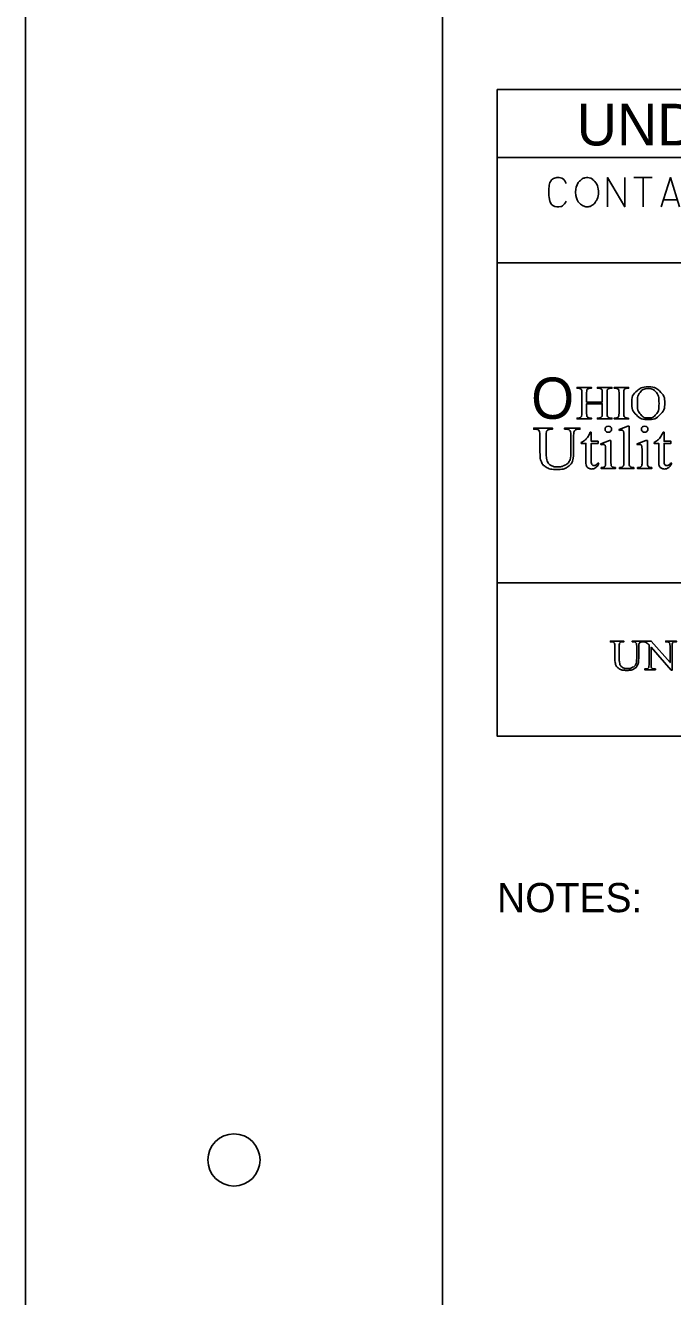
# Model space of a CAD drawing. Extents: x 0 to 34, y 0 to 22.
# Drawn here: x 0 to 3.1, y 6.09 to 12.19 of the extents above; entities that cross this region are included whole.
import ezdxf

# ---------------------------------------------------------------- set-up
doc = ezdxf.new("R2010")
doc.units = 0
for name, color, linetype in [('SH_Border', 7, 'Continuous'), ('SH_Cut_Line', 7, 'Continuous'), ('SH_Data', 7, 'Continuous'), ('SH_Text', 7, 'Continuous')]:
    doc.layers.add(name, color=color, linetype=linetype)

msp = doc.modelspace()

# ---------------------------------------------------------------- linework, layer by layer
at = {"layer": 'SH_Border'}
msp.add_lwpolyline([(2, 21.5), (33.5, 21.5), (33.5, 0.5), (2, 0.5)], close=True, dxfattribs=at)
msp.add_circle((1, 6.75), 0.125, dxfattribs=at)
at = {"layer": 'SH_Cut_Line'}
msp.add_lwpolyline([(0, 0), (34, 0), (34, 22), (0, 22)], close=True, dxfattribs=at)
at = {"layer": 'SH_Data'}
for p, q in [((2.2617, 11.5571), (7.4617, 11.5571)), ((2.918, 11.46), (3.0051, 11.46)), ((2.9621, 11.46), (2.9621, 11.32)), ((3.1253, 11.3531), (3.0602, 11.3531)), ((2.2617, 11.0512), (7.4617, 11.0512)), ((2.2617, 9.5165), (7.4617, 9.5165))]:
    msp.add_line(p, q, dxfattribs=at)
msp.add_lwpolyline([(2.2617, 11.8822), (7.4617, 11.8822), (7.4617, 8.7822), (2.2617, 8.7822)], close=True, dxfattribs=at)
msp.add_lwpolyline([(2.2617, 11.8822), (7.4617, 11.8822), (7.4617, 8.7822), (2.2617, 8.7822)], close=True, dxfattribs=at)
for points in [[(2.5929, 11.4325), (2.5874, 11.4446), (2.5818, 11.4512), (2.5763, 11.4556), (2.5719, 11.4578), (2.5598, 11.46), (2.5477, 11.46), (2.5322, 11.4556), (2.5234, 11.449), (2.519, 11.4435), (2.5146, 11.4358), (2.5113, 11.4237), (2.5102, 11.4016), (2.5102, 11.3851), (2.5102, 11.374), (2.5113, 11.3641), (2.5146, 11.3465), (2.5157, 11.3432), (2.5201, 11.3355), (2.5245, 11.33), (2.5322, 11.3244), (2.5389, 11.3222), (2.5477, 11.32), (2.5576, 11.32), (2.5675, 11.3211), (2.5708, 11.3222), (2.5752, 11.3244), (2.5796, 11.3289), (2.5851, 11.3344), (2.5896, 11.341), (2.5929, 11.3465)], [(2.6821, 11.4589), (2.6788, 11.4578), (2.6755, 11.4567), (2.67, 11.4534), (2.6667, 11.4512), (2.6612, 11.4468), (2.6568, 11.4424), (2.6546, 11.4402), (2.6513, 11.4358), (2.6458, 11.4247), (2.6414, 11.4137), (2.6392, 11.4038), (2.6381, 11.3895), (2.6392, 11.374), (2.6425, 11.363), (2.6458, 11.3542), (2.648, 11.3498), (2.6513, 11.3443), (2.6557, 11.3388), (2.659, 11.3355), (2.6623, 11.3322), (2.6667, 11.3289), (2.6722, 11.3255), (2.6821, 11.3211), (2.6877, 11.32), (2.6987, 11.32), (2.7031, 11.3211), (2.7075, 11.3222), (2.713, 11.3244), (2.7185, 11.3277), (2.7218, 11.33), (2.7251, 11.3322), (2.7284, 11.3355), (2.7317, 11.3399), (2.7339, 11.3432), (2.7362, 11.3465), (2.7384, 11.3498), (2.7417, 11.3564), (2.745, 11.3641), (2.7472, 11.3729), (2.7483, 11.3807), (2.7483, 11.3818), (2.7483, 11.3895), (2.7483, 11.3961), (2.7472, 11.4049), (2.745, 11.4137), (2.7428, 11.4203), (2.7395, 11.4281), (2.7362, 11.4347), (2.7306, 11.4413), (2.7262, 11.4457), (2.7218, 11.4501), (2.7174, 11.4534), (2.7108, 11.4567), (2.7042, 11.4589), (2.6976, 11.46), (2.6899, 11.46), (2.6821, 11.4589)], [(2.7913, 11.32), (2.7913, 11.46), (2.8739, 11.32), (2.8739, 11.46)], [(3.0492, 11.32), (3.0933, 11.46), (3.1363, 11.32)], [(2.651, 10.4499), (2.6453, 10.4499), (2.6453, 10.454), (2.7144, 10.454), (2.7144, 10.4499), (2.7086, 10.4499)], [(2.6684, 10.33), (2.6684, 10.4273)], [(2.6913, 10.3841), (2.7664, 10.3841), (2.7664, 10.4273)], [(2.6913, 10.4273), (2.6913, 10.3841)], [(2.749, 10.4499), (2.7433, 10.4499), (2.7433, 10.454), (2.8124, 10.454), (2.8124, 10.4499), (2.8067, 10.4499)], [(2.7893, 10.4273), (2.7893, 10.33)], [(2.8292, 10.4499), (2.8235, 10.4499), (2.8235, 10.454), (2.8926, 10.454), (2.8926, 10.4499), (2.8868, 10.4499)], [(2.8466, 10.33), (2.8466, 10.4273)], [(2.8695, 10.4273), (2.8695, 10.33)], [(2.7664, 10.33), (2.7664, 10.3758), (2.6913, 10.3758), (2.6913, 10.33)], [(2.7086, 10.3074), (2.7144, 10.3074), (2.7144, 10.3033), (2.6453, 10.3033), (2.6453, 10.3074), (2.651, 10.3074)], [(2.8067, 10.3074), (2.8124, 10.3074), (2.8124, 10.3033), (2.7433, 10.3033), (2.7433, 10.3074), (2.749, 10.3074)], [(2.8926, 10.3074), (2.8926, 10.3033), (2.8235, 10.3033), (2.8235, 10.3074), (2.8292, 10.3074)], [(2.8868, 10.3074), (2.8926, 10.3074)], [(2.4452, 10.2535), (2.4374, 10.2535), (2.4374, 10.2587), (2.5272, 10.2587), (2.5272, 10.2535), (2.5193, 10.2535)], [(2.5857, 10.2535), (2.5857, 10.2587), (2.6589, 10.2587), (2.6589, 10.2535), (2.6511, 10.2535)], [(2.5934, 10.2535), (2.5857, 10.2535)], [(2.8492, 10.247), (2.8466, 10.2522), (2.8884, 10.2682), (2.8953, 10.2682)], [(2.8953, 10.2682), (2.8953, 10.0946)], [(2.4676, 10.1488), (2.4676, 10.2244)], [(2.497, 10.2244), (2.497, 10.1401)], [(2.6154, 10.1461), (2.6154, 10.2244)], [(2.6291, 10.2233), (2.6291, 10.1448)], [(2.6877, 10.0979), (2.6877, 10.1859), (2.6655, 10.1859), (2.6655, 10.1906)], [(2.7085, 10.2389), (2.7132, 10.2389)], [(2.7132, 10.2389), (2.7132, 10.1959), (2.746, 10.1959), (2.746, 10.1859), (2.7132, 10.1859), (2.7132, 10.101)], [(2.7611, 10.1785), (2.7589, 10.1837), (2.8013, 10.1997), (2.808, 10.1997)], [(2.808, 10.1997), (2.808, 10.0946)], [(2.8698, 10.0946), (2.8698, 10.2135)], [(2.9357, 10.1785), (2.9335, 10.1837), (2.9759, 10.1997), (2.9826, 10.1997)], [(2.9826, 10.1997), (2.9826, 10.0946)], [(3.037, 10.0979), (3.037, 10.1859), (3.0147, 10.1859), (3.0147, 10.1906)], [(3.0577, 10.2389), (3.0624, 10.2389)], [(3.0624, 10.2389), (3.0624, 10.1959), (3.0953, 10.1959), (3.0953, 10.1859), (3.0624, 10.1859), (3.0624, 10.101)], [(2.7825, 10.0946), (2.7825, 10.145)], [(2.9571, 10.0946), (2.9571, 10.145)], [(2.7445, 10.091), (2.7504, 10.091)], [(2.8292, 10.0703), (2.8292, 10.0651), (2.7611, 10.0651), (2.7611, 10.0703)], [(2.9181, 10.0703), (2.9181, 10.0651), (2.8489, 10.0651), (2.8489, 10.0703)], [(3.0038, 10.0703), (3.0038, 10.0651), (2.9357, 10.0651), (2.9357, 10.0703)], [(3.0937, 10.091), (3.0996, 10.091)], [(2.811, 9.2337), (2.8054, 9.2337), (2.8054, 9.2374), (2.869, 9.2374), (2.869, 9.2337), (2.8633, 9.2337)], [(2.8268, 9.1597), (2.8268, 9.2132)], [(2.8476, 9.2132), (2.8476, 9.1536)], [(2.9103, 9.2337), (2.9103, 9.2374), (2.962, 9.2374), (2.962, 9.2337), (2.9565, 9.2337)], [(2.9157, 9.2337), (2.9103, 9.2337)], [(2.9313, 9.1578), (2.9313, 9.2132)], [(2.941, 9.2124), (2.941, 9.1569)], [(2.9616, 9.2374), (3.0013, 9.2374), (3.0913, 9.1347), (3.0913, 9.2137)], [(2.9616, 9.2337), (2.9616, 9.2374)], [(2.9906, 9.1243), (2.9906, 9.2194)], [(3.1008, 9.2137), (3.1008, 9.0983), (3.0969, 9.0983), (3.0001, 9.2086), (3.0001, 9.1243)], [(3.0756, 9.2337), (3.0705, 9.2337), (3.0705, 9.2374), (3.1215, 9.2374), (3.1215, 9.2337), (3.1164, 9.2337)], [(3.0156, 9.1042), (3.0208, 9.1042), (3.0208, 9.1006), (2.9698, 9.1006), (2.9698, 9.1042), (2.9749, 9.1042)]]:
    msp.add_lwpolyline(points, dxfattribs=at)
for points in [[(2.6684, 10.4273), (2.6684, 10.4388), (2.6669, 10.4425), (2.6657, 10.4453), (2.662, 10.4473), (2.6567, 10.4499), (2.651, 10.4499)], [(2.7086, 10.4499), (2.7029, 10.4499), (2.6978, 10.4474), (2.6941, 10.4456), (2.6927, 10.442), (2.6913, 10.4384), (2.6913, 10.4273)], [(2.7664, 10.4273), (2.7664, 10.4388), (2.7649, 10.4425), (2.7637, 10.4453), (2.7599, 10.4473), (2.7548, 10.4499), (2.749, 10.4499)], [(2.8067, 10.4499), (2.801, 10.4499), (2.7958, 10.4474), (2.792, 10.4456), (2.7907, 10.442), (2.7893, 10.4384), (2.7893, 10.4273)], [(2.8466, 10.4273), (2.8466, 10.4388), (2.8451, 10.4424), (2.8439, 10.4452), (2.8402, 10.4472), (2.8349, 10.4499), (2.8292, 10.4499)], [(2.8868, 10.4499), (2.8769, 10.4499), (2.8724, 10.4445), (2.8695, 10.4409), (2.8695, 10.4273)], [(2.9881, 10.4574), (3.0196, 10.4574), (3.0427, 10.4351), (3.0658, 10.4129), (3.0658, 10.3795), (3.0658, 10.3452), (3.0425, 10.3226), (3.0193, 10.2999), (2.9862, 10.2999), (2.9528, 10.2999), (2.9301, 10.322), (2.9074, 10.3441), (2.9074, 10.3792), (2.9074, 10.4151), (2.9336, 10.4378), (2.9564, 10.4574), (2.9881, 10.4574)], [(2.9859, 10.4493), (2.9642, 10.4493), (2.9511, 10.4343), (2.9347, 10.4156), (2.9347, 10.3796), (2.9347, 10.3428), (2.9517, 10.3229), (2.9647, 10.3078), (2.986, 10.3078), (3.0088, 10.3078), (3.0236, 10.3243), (3.0384, 10.3409), (3.0384, 10.3765), (3.0384, 10.4152), (3.0221, 10.4342), (3.009, 10.4493), (2.9859, 10.4493)], [(2.651, 10.3074), (2.661, 10.3074), (2.6656, 10.3129), (2.6684, 10.3164), (2.6684, 10.33)], [(2.6913, 10.33), (2.6913, 10.3186), (2.6928, 10.3149), (2.694, 10.3121), (2.6978, 10.3101), (2.7029, 10.3074), (2.7086, 10.3074)], [(2.749, 10.3074), (2.7589, 10.3074), (2.7635, 10.3129), (2.7664, 10.3164), (2.7664, 10.33)], [(2.7893, 10.33), (2.7893, 10.3186), (2.7908, 10.3149), (2.792, 10.3121), (2.7957, 10.3101), (2.801, 10.3074), (2.8067, 10.3074)], [(2.8292, 10.3074), (2.8392, 10.3074), (2.8438, 10.3129), (2.8466, 10.3164), (2.8466, 10.33)], [(2.8695, 10.33), (2.8695, 10.3186), (2.871, 10.3149), (2.8722, 10.3121), (2.876, 10.3101), (2.8811, 10.3074), (2.8868, 10.3074)], [(2.4676, 10.2244), (2.4676, 10.2423), (2.4623, 10.2479), (2.457, 10.2535), (2.4452, 10.2535)], [(2.5193, 10.2535), (2.5064, 10.2535), (2.5008, 10.2459), (2.497, 10.2407), (2.497, 10.2244)], [(2.6154, 10.2244), (2.6154, 10.2426), (2.6111, 10.2472), (2.6052, 10.2535), (2.5934, 10.2535)], [(2.6511, 10.2535), (2.6389, 10.2535), (2.6323, 10.2439), (2.6291, 10.2395), (2.6291, 10.2233)], [(2.7953, 10.2682), (2.8017, 10.2682), (2.8062, 10.264), (2.8107, 10.2598), (2.8107, 10.2538), (2.8107, 10.2478), (2.8062, 10.2435), (2.8017, 10.2393), (2.7953, 10.2393), (2.7888, 10.2393), (2.7842, 10.2435), (2.7796, 10.2478), (2.7796, 10.2538), (2.7796, 10.2598), (2.7842, 10.264), (2.7887, 10.2682), (2.7953, 10.2682)], [(2.8698, 10.2135), (2.8698, 10.2355), (2.8688, 10.2405), (2.8677, 10.2456), (2.8653, 10.2474), (2.8629, 10.2493), (2.8593, 10.2493), (2.8553, 10.2493), (2.8492, 10.247)], [(2.9699, 10.2682), (2.9763, 10.2682), (2.9808, 10.264), (2.9853, 10.2598), (2.9853, 10.2538), (2.9853, 10.2478), (2.9808, 10.2435), (2.9763, 10.2393), (2.9699, 10.2393), (2.9634, 10.2393), (2.9588, 10.2435), (2.9542, 10.2478), (2.9542, 10.2538), (2.9542, 10.2598), (2.9588, 10.264), (2.9633, 10.2682), (2.9699, 10.2682)], [(2.6655, 10.1906), (2.6739, 10.1938), (2.6828, 10.2013), (2.6916, 10.2088), (2.6986, 10.2191), (2.7021, 10.2245), (2.7085, 10.2389)], [(2.7825, 10.145), (2.7825, 10.1662), (2.7811, 10.1725), (2.7801, 10.1771), (2.7778, 10.1789), (2.7755, 10.1806), (2.7715, 10.1806), (2.7672, 10.1806), (2.7611, 10.1785)], [(2.9571, 10.145), (2.9571, 10.1662), (2.9558, 10.1725), (2.9547, 10.1771), (2.9524, 10.1789), (2.9501, 10.1806), (2.9461, 10.1806), (2.9418, 10.1806), (2.9357, 10.1785)], [(3.0147, 10.1906), (3.0232, 10.1938), (3.032, 10.2013), (3.0408, 10.2088), (3.0478, 10.2191), (3.0513, 10.2245), (3.0577, 10.2389)], [(2.6291, 10.1448), (2.6291, 10.1157), (2.6229, 10.0996), (2.6167, 10.0836), (2.5986, 10.0721), (2.5804, 10.0606), (2.5492, 10.0606), (2.5151, 10.0606), (2.4975, 10.0716), (2.4799, 10.0826), (2.4725, 10.1011), (2.4676, 10.1138), (2.4676, 10.1488)], [(2.497, 10.1401), (2.497, 10.1289), (2.4992, 10.1143), (2.5015, 10.0998), (2.5073, 10.0916), (2.5131, 10.0835), (2.5241, 10.0782), (2.535, 10.073), (2.551, 10.073), (2.5714, 10.073), (2.5875, 10.0812), (2.6036, 10.0895), (2.6095, 10.1024), (2.6154, 10.1153), (2.6154, 10.1461)], [(2.7504, 10.091), (2.745, 10.077), (2.7352, 10.0699), (2.7253, 10.0628), (2.7148, 10.0628), (2.7078, 10.0628), (2.701, 10.0665), (2.6942, 10.0701), (2.691, 10.0769), (2.6877, 10.0837), (2.6877, 10.0979)], [(2.7132, 10.101), (2.7132, 10.0883), (2.7172, 10.0839), (2.7211, 10.0795), (2.7272, 10.0795), (2.7323, 10.0795), (2.7371, 10.0824), (2.7419, 10.0853), (2.7445, 10.091)], [(2.7611, 10.0703), (2.7714, 10.0703), (2.7749, 10.0721), (2.7784, 10.074), (2.7805, 10.0783), (2.7825, 10.0825), (2.7825, 10.0946)], [(2.808, 10.0946), (2.808, 10.0824), (2.8099, 10.0783), (2.8118, 10.0743), (2.8156, 10.0723), (2.8193, 10.0703), (2.8292, 10.0703)], [(2.8489, 10.0703), (2.8587, 10.0703), (2.8622, 10.0721), (2.8658, 10.074), (2.8678, 10.0783), (2.8698, 10.0825), (2.8698, 10.0946)], [(2.8953, 10.0946), (2.8953, 10.0824), (2.8972, 10.0784), (2.8992, 10.0744), (2.9031, 10.0723), (2.9071, 10.0703), (2.9181, 10.0703)], [(2.9357, 10.0703), (2.946, 10.0703), (2.9495, 10.0721), (2.953, 10.074), (2.9551, 10.0783), (2.9571, 10.0825), (2.9571, 10.0946)], [(2.9826, 10.0946), (2.9826, 10.0824), (2.9845, 10.0783), (2.9864, 10.0743), (2.9902, 10.0723), (2.9939, 10.0703), (3.0038, 10.0703)], [(3.0996, 10.091), (3.0942, 10.077), (3.0844, 10.0699), (3.0745, 10.0628), (3.0641, 10.0628), (3.057, 10.0628), (3.0502, 10.0665), (3.0434, 10.0701), (3.0402, 10.0769), (3.037, 10.0837), (3.037, 10.0979)], [(3.0624, 10.101), (3.0624, 10.0883), (3.0664, 10.0839), (3.0703, 10.0795), (3.0764, 10.0795), (3.0815, 10.0795), (3.0863, 10.0824), (3.0911, 10.0853), (3.0937, 10.091)], [(2.8268, 9.2132), (2.8268, 9.2258), (2.8231, 9.2298), (2.8193, 9.2337), (2.811, 9.2337)], [(2.8633, 9.2337), (2.8542, 9.2337), (2.8503, 9.2284), (2.8476, 9.2247), (2.8476, 9.2132)], [(2.9313, 9.2132), (2.9313, 9.226), (2.9282, 9.2293), (2.924, 9.2337), (2.9157, 9.2337)], [(2.9565, 9.2337), (2.9479, 9.2337), (2.9432, 9.227), (2.941, 9.2238), (2.941, 9.2124)], [(2.9906, 9.2194), (2.9842, 9.2264), (2.9809, 9.2287), (2.9776, 9.2309), (2.9712, 9.2328), (2.968, 9.2337), (2.9616, 9.2337)], [(3.0913, 9.2137), (3.0913, 9.2264), (3.0883, 9.2295), (3.0843, 9.2337), (3.0756, 9.2337)], [(3.1164, 9.2337), (3.107, 9.2337), (3.1032, 9.2285), (3.1008, 9.2253), (3.1008, 9.2137)], [(2.941, 9.1569), (2.941, 9.1364), (2.9366, 9.125), (2.9322, 9.1137), (2.9194, 9.1055), (2.9065, 9.0974), (2.8844, 9.0974), (2.8604, 9.0974), (2.8479, 9.1052), (2.8355, 9.113), (2.8303, 9.1261), (2.8268, 9.135), (2.8268, 9.1597)], [(2.8476, 9.1536), (2.8476, 9.1457), (2.8492, 9.1354), (2.8507, 9.1251), (2.8548, 9.1193), (2.859, 9.1136), (2.8667, 9.1099), (2.8745, 9.1061), (2.8857, 9.1061), (2.9002, 9.1061), (2.9115, 9.112), (2.9229, 9.1178), (2.9271, 9.127), (2.9313, 9.1361), (2.9313, 9.1578)], [(2.9749, 9.1042), (2.9843, 9.1042), (2.9882, 9.1095), (2.9906, 9.1127), (2.9906, 9.1243)], [(3.0001, 9.1243), (3.0001, 9.1116), (3.003, 9.1085), (3.0071, 9.1042), (3.0156, 9.1042)]]:
    msp.add_open_spline(points, degree=3, dxfattribs=at)

# ---------------------------------------------------------------- texts
for s, height, p in [('UNDERGROUND UTILITIES', 0.2, (2.6436, 11.6141)), ('O', 0.1981, (2.4254, 10.3033))]:
    msp.add_text(s, height=height, dxfattribs=at).set_placement(p)
at = {"layer": 'SH_Text'}
msp.add_text('NOTES:', height=0.14, dxfattribs=at).set_placement((2.2617, 7.9379))

doc.saveas('drawing.dxf')
